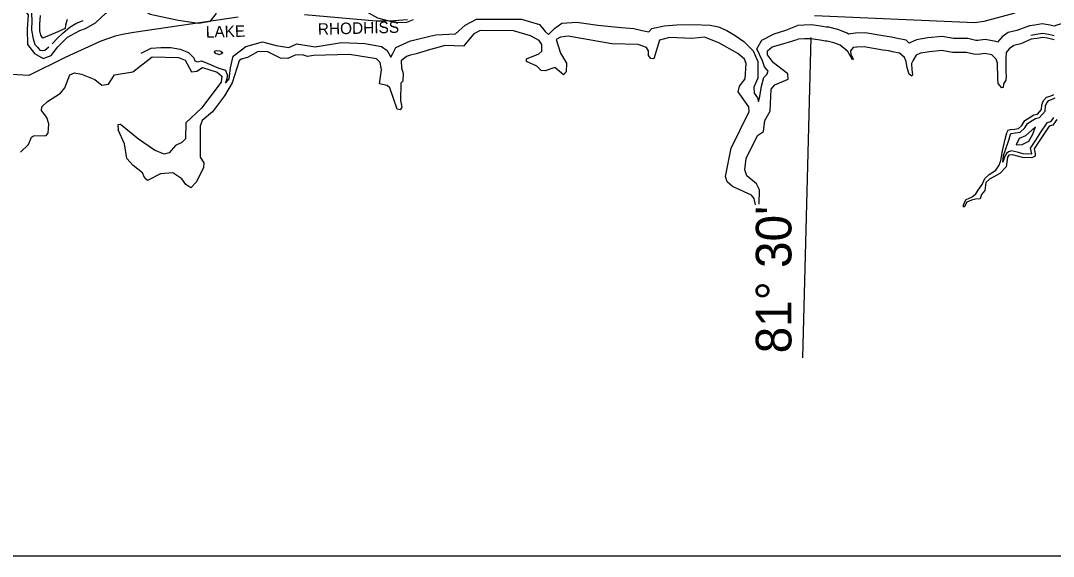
# Model space of a CAD drawing. Extents: x 1159738 to 1321356, y 736314 to 882035.
# Drawn here: x 1244144 to 1262980, y 738580 to 748344 of the extents above; entities that cross this region are included whole.
import ezdxf

# ---------------------------------------------------------------- set-up
doc = ezdxf.new("R2010")
doc.units = 0
for name, color, linetype in [('Exist Boundary Political CountyLine', 7, 'Continuous'), ('Exist Hydrographic Buffer Line', 7, 'Continuous'), ('Exist Hydrographic Island Shore', 7, 'Continuous'), ('Exist Hydrographic Lake Shore', 7, 'Continuous'), ('Exist Hydrographic River Shore Label', 7, 'Continuous'), ('Map Preparation Inset Cut Line', 7, 'Continuous'), ('Map Preparation Longitude Latitude Label', 7, 'Continuous'), ('Map Preparation Longitude Latitude Lines', 7, 'Continuous')]:
    doc.layers.add(name, color=color, linetype=linetype)

msp = doc.modelspace()

# ---------------------------------------------------------------- linework, layer by layer
at = {"layer": 'Exist Boundary Political CountyLine'}
for points in [[(1248114, 748407), (1246211, 748130), (1246031, 748099), (1245870, 748062), (1245604, 747970), (1244954, 747671), (1244293, 747346), (1242684, 747436)], [(1251200, 748362), (1250954, 748339), (1250804, 748332), (1250628, 748333), (1249321, 748451)], [(1262275, 748483), (1261713, 748326), (1261551, 748307), (1258625, 748433)]]:
    msp.add_lwpolyline(points, dxfattribs=at)
at = {"layer": 'Exist Hydrographic Buffer Line'}
for p, q in [((1262655, 746410), (1262473, 746246)), ((1262609, 746273), (1262655, 746410)), ((1262356, 746196), (1262304, 746078)), ((1262304, 746078), (1262412, 746087)), ((1262473, 746246), (1262356, 746196)), ((1262412, 746087), (1262534, 746146)), ((1262534, 746146), (1262609, 746273))]:
    msp.add_line(p, q, dxfattribs=at)
for points in [[(1242818, 749288), (1242915, 749318), (1243273, 748968), (1243374, 748918), (1243475, 748862), (1243607, 748791), (1243834, 748730), (1244016, 748680), (1244123, 748629), (1244330, 748584), (1244345, 748462), (1244350, 748346), (1244343, 748170), (1244371, 748011), (1244406, 747910), (1244452, 747860), (1244497, 747804), (1244543, 747799), (1244588, 747809), (1244659, 747865)], [(1245325, 748201), (1245510, 748305), (1245700, 748481), (1245945, 748670), (1246088, 748832), (1246102, 748929), (1246134, 748994), (1246171, 748971), (1246194, 748883), (1246185, 748744), (1246227, 748629), (1246351, 748550), (1246509, 748462), (1247017, 748351), (1247387, 748300), (1247608, 748337), (1247710, 748471), (1247803, 748971), (1248052, 748915), (1248505, 748860), (1248861, 748864), (1249138, 748897)], [(1249138, 748897), (1249591, 748864), (1249942, 748809), (1250090, 748837), (1250210, 748744), (1250488, 748485), (1250654, 748393), (1250978, 748310), (1251190, 748319), (1251312, 748368)], [(1244096, 748558), (1244225, 748516), (1244280, 748451), (1244262, 748192), (1244271, 747910), (1244396, 747744), (1244553, 747656), (1244701, 747711), (1244821, 747869), (1245001, 748044), (1245223, 748164), (1245325, 748201)], [(1251609, 748062), (1251717, 748088), (1252077, 748106), (1252253, 748263), (1252456, 748374), (1252845, 748374), (1253279, 748374)], [(1253279, 748374), (1253607, 748277), (1253709, 748148), (1253773, 748092), (1253884, 748203), (1254014, 748296), (1254291, 748314), (1254670, 748259), (1255095, 748222), (1255326, 748203), (1255483, 748166), (1255604, 748138), (1255659, 748203), (1255881, 748249), (1256112, 748268), (1256408, 748277), (1256722, 748259), (1256870, 748231), (1257027, 748166), (1257175, 748074), (1257332, 747963), (1257508, 747796), (1257591, 747602), (1257591, 747297), (1257517, 747130), (1257526, 747020), (1257582, 746936), (1257600, 746872), (1257628, 746964), (1257655, 747149), (1257702, 747306), (1257757, 747362), (1257776, 747426), (1257711, 747500), (1257674, 747611), (1257572, 747833), (1257665, 747991), (1257887, 748101), (1258098, 748172), (1258316, 748258)], [(1244720, 747920), (1244816, 748027), (1244917, 748123), (1245039, 748224), (1245150, 748290), (1245287, 748346)], [(1262544, 748248), (1262312, 748162), (1262158, 748127), (1262048, 748052), (1261960, 747952), (1261933, 747963), (1261738, 747999), (1261604, 747983), (1261566, 747985), (1261422, 748020), (1261279, 748020), (1261161, 748016), (1260955, 748056), (1260689, 748028), (1260483, 747997), (1260352, 747934), (1260293, 747988), (1260105, 748023), (1260030, 748044), (1259909, 748060), (1259549, 748121), (1259373, 748115), (1259246, 748097), (1259221, 748118), (1259051, 748180), (1258886, 748225), (1258838, 748225), (1258770, 748236), (1258573, 748269), (1258434, 748263), (1258316, 748258)], [(1264584, 748218), (1264259, 748336), (1264127, 748296), (1264114, 748294), (1264091, 748300), (1264010, 748324), (1263862, 748318), (1263730, 748312), (1263623, 748277), (1263542, 748267), (1263473, 748264), (1263413, 748264), (1263385, 748270), (1263230, 748315), (1263042, 748259), (1262995, 748245), (1262924, 748264), (1262778, 748285), (1262642, 748261), (1262544, 748248)], [(1247883, 747207), (1247946, 747283), (1247974, 747487), (1248020, 747699), (1248251, 747875), (1248556, 747958), (1248805, 747893), (1249037, 747856), (1249184, 747921), (1249517, 747866), (1249998, 747949), (1250423, 747930), (1250728, 747875), (1250830, 747801), (1250894, 747681), (1250931, 747745), (1250987, 747856), (1251255, 747977), (1251336, 747996)], [(1251336, 747996), (1251609, 748062)], [(1262996, 748065), (1262889, 748093), (1262781, 748109), (1262668, 748089), (1262567, 748076)], [(1246342, 747753), (1246525, 747840), (1246700, 747854), (1246885, 747854), (1247052, 747826), (1247204, 747766), (1247306, 747665), (1247324, 747614), (1247370, 747591), (1247440, 747614), (1247546, 747567), (1247759, 747480), (1247879, 747443), (1247916, 747336), (1247883, 747207)], [(1262171, 746165), (1262197, 746275), (1262203, 746286), (1262216, 746290), (1262281, 746298), (1262372, 746310), (1262462, 746391), (1262510, 746472), (1262594, 746524), (1262654, 746563), (1262730, 746579), (1262831, 746697), (1262837, 746794), (1262860, 746849), (1262896, 746886), (1262949, 746905), (1263015, 746937)], [(1262985, 746580), (1262927, 746499), (1262860, 746480), (1262747, 746313), (1262653, 746167), (1262558, 746021), (1262580, 745916), (1262574, 745913), (1262428, 745917), (1262346, 745942), (1262240, 745968), (1262215, 745969), (1262162, 745953), (1262124, 745921), (1262098, 745871), (1262059, 745765), (1262074, 745884), (1262105, 745992), (1262171, 746165)]]:
    msp.add_lwpolyline(points, dxfattribs=at)
at = {"layer": 'Exist Hydrographic Island Shore'}
msp.add_lwpolyline([(1247680, 747777), (1247689, 747792), (1247723, 747799), (1247772, 747792), (1247794, 747788), (1247833, 747758), (1247810, 747740), (1247780, 747729), (1247764, 747721), (1247742, 747733), (1247710, 747740), (1247702, 747744)], close=True, dxfattribs=at)
at = {"layer": 'Exist Hydrographic Lake Shore'}
for points in [[(1244991, 748363), (1244963, 748260), (1244956, 748201), (1244820, 748142), (1244550, 748027), (1244513, 748077), (1244492, 748157), (1244495, 748281), (1244504, 748441)], [(1252523, 748167), (1252413, 748104), (1252224, 747881), (1251883, 747891), (1251779, 747862)], [(1257547, 744984), (1257522, 745103), (1257474, 745163), (1257128, 745321), (1257030, 745408), (1256999, 745501), (1257104, 746021), (1257430, 746690), (1257424, 746772), (1257231, 747045), (1257258, 747153), (1257362, 747282), (1257378, 747564), (1257346, 747641), (1257224, 747745), (1256879, 747939), (1256615, 748046), (1256389, 748018), (1255980, 748036), (1255796, 747990), (1255695, 747651), (1255637, 747652), (1255597, 747712), (1255599, 747794), (1255559, 747854), (1255410, 747909), (1254927, 747922), (1254130, 748060), (1253988, 748046), (1253912, 747998), (1253989, 747754), (1254101, 747568), (1254096, 747410), (1254045, 747359), (1253890, 747490), (1253713, 747428), (1253638, 747436), (1253557, 747513), (1253368, 747602), (1253369, 747651), (1253596, 747739), (1253648, 747787), (1253651, 747912), (1253603, 747982), (1253446, 748067), (1253132, 748158), (1252523, 748167)], [(1257612, 744999), (1257618, 745259), (1257563, 745368), (1257391, 745516), (1257353, 745625), (1257375, 745831), (1257585, 746251), (1257696, 746324), (1257717, 746524), (1257814, 746696), (1257832, 747096), (1257901, 747176), (1258146, 747280), (1258140, 747372), (1257878, 747577), (1257765, 747724), (1257767, 747796), (1257852, 747870), (1258088, 747931), (1258326, 748005)], [(1262576, 748007), (1262389, 747919), (1262261, 747890), (1262177, 747833), (1262118, 747762), (1262113, 747657), (1262113, 747533), (1262113, 747409), (1262118, 747328), (1262113, 747261), (1262069, 747190), (1262064, 747128), (1262040, 747118), (1261976, 747199), (1261966, 747285), (1261966, 747376), (1261961, 747490), (1261961, 747571), (1261937, 747643), (1261858, 747719), (1261730, 747743), (1261612, 747728), (1261529, 747733), (1261391, 747766), (1261283, 747766), (1261141, 747762), (1260944, 747800), (1260721, 747776), (1260559, 747752), (1260480, 747714), (1260421, 747624), (1260392, 747562), (1260397, 747447), (1260411, 747361), (1260397, 747333), (1260352, 747371), (1260313, 747485), (1260293, 747600), (1260264, 747671), (1260176, 747752), (1260048, 747776), (1259979, 747795), (1259871, 747809), (1259532, 747867), (1259395, 747862), (1259326, 747852), (1259279, 747795), (1259289, 747728), (1259328, 747647), (1259318, 747628), (1259230, 747781), (1259092, 747895), (1258975, 747938), (1258852, 747971), (1258817, 747971), (1258729, 747986), (1258557, 748014), (1258444, 748010), (1258326, 748005)], [(1262997, 747993), (1262875, 748025), (1262782, 748039), (1262679, 748020), (1262576, 748007)], [(1251619, 747816), (1251361, 747742)], [(1251779, 747862), (1251619, 747816)], [(1244144, 745949), (1244290, 746087), (1244343, 746218), (1244377, 746243), (1244611, 746252), (1244645, 746294), (1244658, 746461), (1244619, 746576), (1244522, 746706), (1244532, 746772), (1244635, 746868), (1244872, 747021), (1244950, 747118), (1245040, 747359), (1245124, 747390), (1245257, 747371), (1245496, 747271), (1245627, 747170), (1245744, 747184), (1245857, 747356), (1246192, 747411), (1246541, 747687), (1247024, 747674), (1247148, 747622), (1247259, 747410), (1247359, 747424), (1247461, 747488), (1247726, 747407), (1247816, 747330), (1247804, 747221), (1247442, 746746), (1247160, 746479), (1247152, 746187), (1247084, 746123), (1246966, 746066), (1246854, 745937), (1246762, 745913), (1246588, 745985), (1246293, 746185), (1245967, 746451), (1245917, 746445), (1245923, 746353)], [(1251257, 747713), (1251185, 747692), (1251083, 747612), (1251088, 747487), (1251119, 747378), (1251115, 747244), (1251081, 747202), (1251073, 746887), (1251095, 746768), (1251069, 746719), (1251010, 746730), (1250879, 747117), (1250830, 747161), (1250689, 747190), (1250729, 747445), (1250699, 747580), (1250634, 747647), (1250144, 747726), (1249485, 747710), (1249376, 747689), (1249285, 747724), (1249151, 747713), (1249016, 747657), (1248883, 747659), (1248653, 747776), (1248478, 747779), (1248283, 747675), (1248166, 747644), (1248131, 747612), (1248004, 747208), (1247865, 746971), (1247641, 746683), (1247453, 746523), (1247417, 746422), (1247419, 745854), (1247483, 745754), (1247481, 745669), (1247349, 745406), (1247246, 745299), (1247156, 745360), (1247084, 745463), (1246920, 745568), (1246694, 745550), (1246457, 745430), (1246409, 745474), (1246369, 745573), (1246198, 745704), (1246084, 745831), (1246041, 746098), (1245923, 746353)], [(1251361, 747742), (1251257, 747713)], [(1262103, 746181), (1262131, 746299), (1262155, 746345), (1262201, 746358), (1262272, 746368), (1262342, 746377), (1262407, 746436), (1262459, 746522), (1262557, 746583), (1262627, 746629), (1262693, 746642), (1262763, 746724), (1262768, 746810), (1262801, 746888), (1262857, 746947), (1262922, 746969), (1262988, 747001)], [(1263044, 746542), (1262969, 746438), (1262904, 746420), (1262805, 746274), (1262712, 746129), (1262632, 746007), (1262651, 745916), (1262651, 745875), (1262590, 745843), (1262417, 745848), (1262328, 745875), (1262234, 745898), (1262169, 745893), (1262141, 745857), (1262117, 745680), (1262005, 745555), (1261897, 745496), (1261813, 745455), (1261747, 745391), (1261729, 745251), (1261672, 745173), (1261644, 745096), (1261560, 745092), (1261490, 745073), (1261401, 745033), (1261354, 744946), (1261335, 744964), (1261354, 745019), (1261392, 745082), (1261499, 745132), (1261569, 745187), (1261612, 745255), (1261682, 745355), (1261733, 745464), (1261808, 745541), (1261930, 745618), (1261991, 745709), (1262024, 745795), (1262052, 745973), (1262103, 746181)]]:
    msp.add_lwpolyline(points, dxfattribs=at)
at = {"layer": 'Map Preparation Inset Cut Line'}
msp.add_lwpolyline([(1232801, 766757), (1308484, 766757), (1308484, 738580), (1232801, 738580)], close=True, dxfattribs=at)
at = {"layer": 'Map Preparation Longitude Latitude Lines'}
msp.add_line((1258413, 742195), (1258560, 748036), dxfattribs=at)

# ---------------------------------------------------------------- texts
at = {"layer": 'Exist Hydrographic River Shore Label'}
msp.add_text('LAKE                 RHODHISS', height=210, rotation=1.4692, dxfattribs=at).set_placement((1247524, 748033))
at = {"layer": 'Map Preparation Longitude Latitude Label'}
msp.add_text("81° 30'", height=650, rotation=90, dxfattribs=at).set_placement((1258203, 742280))

doc.saveas('drawing.dxf')
